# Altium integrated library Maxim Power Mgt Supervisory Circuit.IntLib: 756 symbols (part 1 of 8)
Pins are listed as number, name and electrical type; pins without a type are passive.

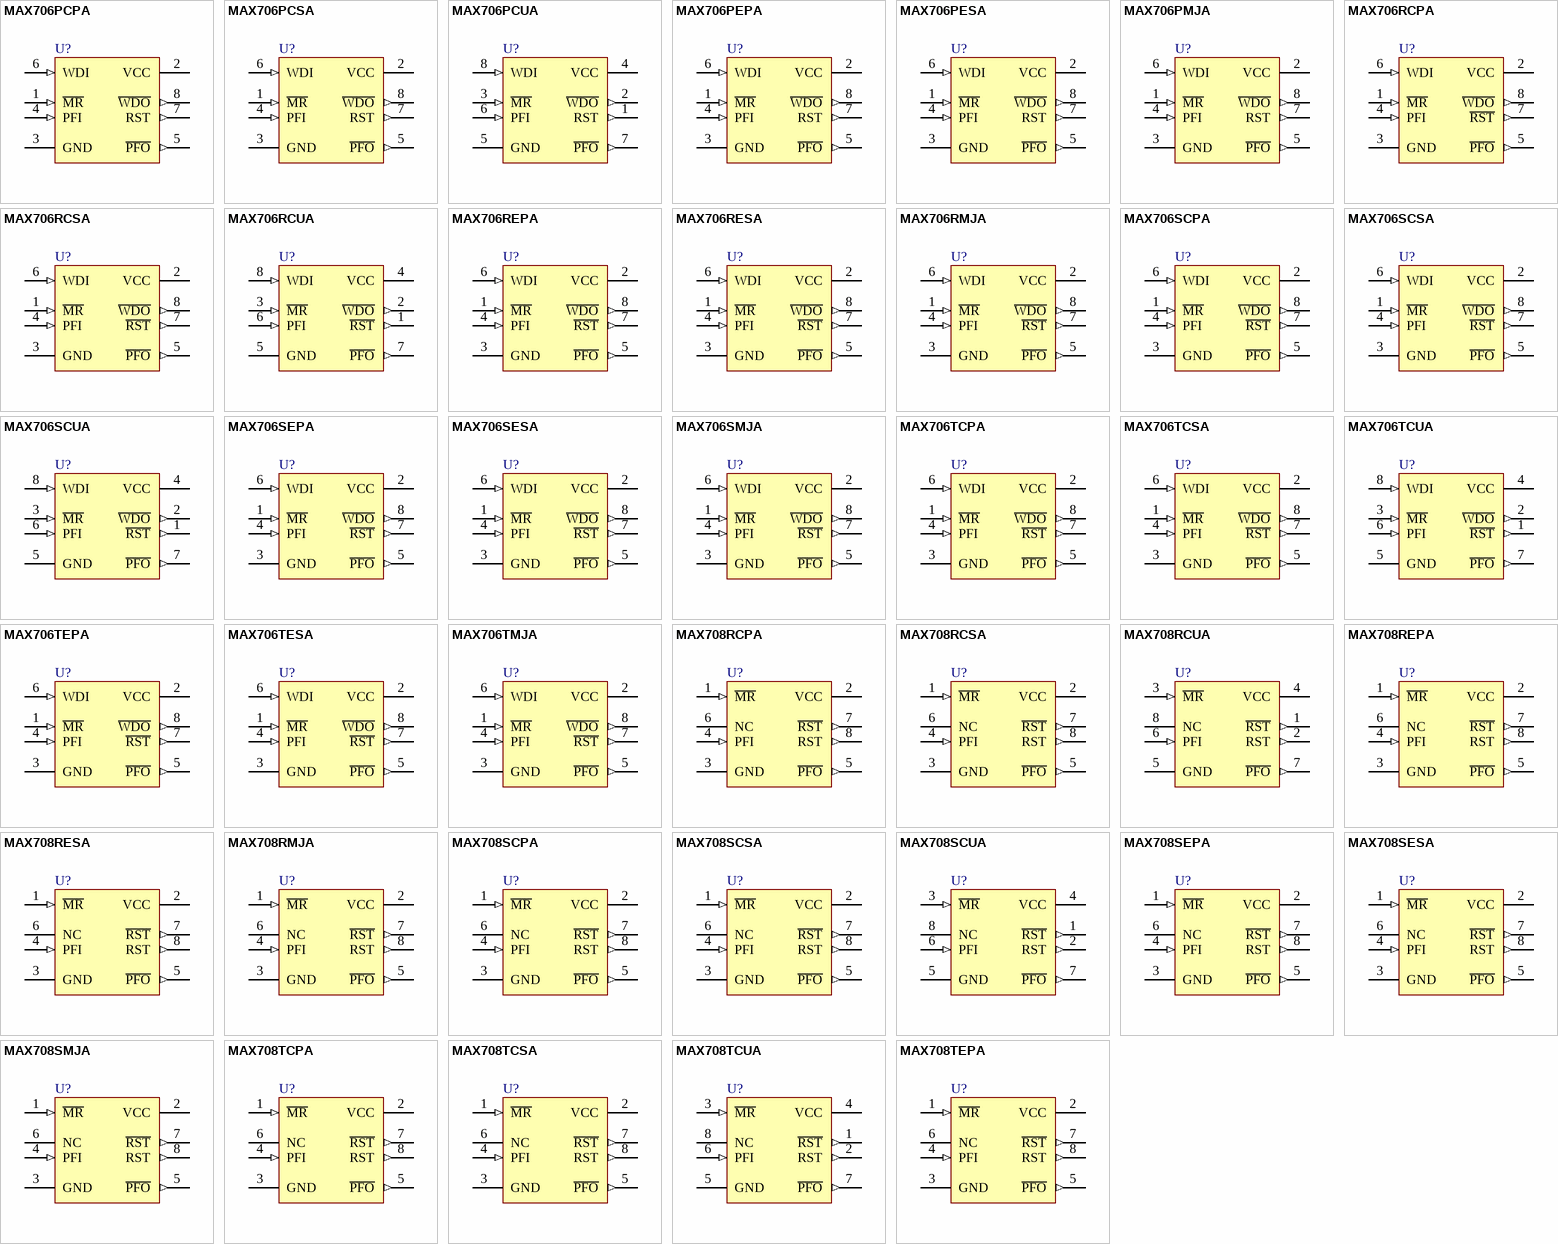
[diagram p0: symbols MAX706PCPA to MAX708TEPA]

## MAX706PCPA
designator U?
+3V Voltage Monitoring, Low-Cost, µP Supervisory Circuit
footprint PA8 (DIP, 8-Leads, Row Spacing 7.62mm, Pitch 2.54mm, Body 9.38x7.24mm)
3D model PA8 (DIP, 8-Pin, Row Spacing 7.62 mm, Pitch 2.54 mm)
pins: 1 ~{MR} (in), 2 VCC (power), 3 GND (power), 4 PFI (in), 5 ~{PFO} (out), 6 WDI (in), 7 RST (out), 8 ~{WDO} (out)

## MAX706PCSA
designator U?
+3V Voltage Monitoring, Low-Cost, µP Supervisory Circuit
footprint NSO8_N (SOIC, 8-Leads, Body 4.9x3.9mm, Pitch 1.27mm, IPC Medium Density)
footprint NSO8_L (SOIC, 8-Leads, Body 4.9x3.9mm, Pitch 1.27mm, IPC High Density)
footprint NSO8_M (SOIC, 8-Leads, Body 4.9x3.9mm, Pitch 1.27mm, IPC Low Density)
3D model NSO8 (8-Pin Small Outline Integrated Circuit 1.27 mm Pitch)
pins: 1 ~{MR} (in), 2 VCC (power), 3 GND (power), 4 PFI (in), 5 ~{PFO} (out), 6 WDI (in), 7 RST (out), 8 ~{WDO} (out)

## MAX706PCUA
designator U?
+3V Voltage Monitoring, Low-Cost, µP Supervisory Circuit
footprint UMAX8_N (TSOP, 8-Leads, Body 3x3mm, Pitch 0.65mm, IPC Medium Density)
footprint UMAX8_L (TSOP, 8-Leads, Body 3x3mm, Pitch 0.65mm, IPC High Density)
footprint UMAX8_M (TSOP, 8-Leads, Body 3x3mm, Pitch 0.65mm, IPC Low Density)
3D model UMAX8 (8-Pin Thin Small Outline Package 0.65 mm Pitch)
pins: 1 RST (out), 2 ~{WDO} (out), 3 ~{MR} (in), 4 VCC (power), 5 GND (power), 6 PFI (in), 7 ~{PFO} (out), 8 WDI (in)

## MAX706PEPA
designator U?
+3V Voltage Monitoring, Low-Cost, µP Supervisory Circuit
footprint PA8 (DIP, 8-Leads, Row Spacing 7.62mm, Pitch 2.54mm, Body 9.38x7.24mm)
3D model PA8 (DIP, 8-Pin, Row Spacing 7.62 mm, Pitch 2.54 mm)
pins: 1 ~{MR} (in), 2 VCC (power), 3 GND (power), 4 PFI (in), 5 ~{PFO} (out), 6 WDI (in), 7 RST (out), 8 ~{WDO} (out)

## MAX706PESA
designator U?
+3V Voltage Monitoring, Low-Cost, µP Supervisory Circuit
footprint NSO8_N (SOIC, 8-Leads, Body 4.9x3.9mm, Pitch 1.27mm, IPC Medium Density)
footprint NSO8_L (SOIC, 8-Leads, Body 4.9x3.9mm, Pitch 1.27mm, IPC High Density)
footprint NSO8_M (SOIC, 8-Leads, Body 4.9x3.9mm, Pitch 1.27mm, IPC Low Density)
3D model NSO8 (8-Pin Small Outline Integrated Circuit 1.27 mm Pitch)
pins: 1 ~{MR} (in), 2 VCC (power), 3 GND (power), 4 PFI (in), 5 ~{PFO} (out), 6 WDI (in), 7 RST (out), 8 ~{WDO} (out)

## MAX706PMJA
designator U?
+3V Voltage Monitoring, Low-Cost, µP Supervisory Circuit
footprint JA8 (DIP, 8-Leads, Row Spacing 7.62mm, Pitch 2.54mm, Body 9.91x6.73mm)
3D model PA8 (DIP, 8-Pin, Row Spacing 7.62 mm, Pitch 2.54 mm)
pins: 1 ~{MR} (in), 2 VCC (power), 3 GND (power), 4 PFI (in), 5 ~{PFO} (out), 6 WDI (in), 7 RST (out), 8 ~{WDO} (out)

## MAX706RCPA
designator U?
+3V Voltage Monitoring, Low-Cost, µP Supervisory Circuit
footprint PA8 (DIP, 8-Leads, Row Spacing 7.62mm, Pitch 2.54mm, Body 9.38x7.24mm)
3D model PA8 (DIP, 8-Pin, Row Spacing 7.62 mm, Pitch 2.54 mm)
pins: 1 ~{MR} (in), 2 VCC (power), 3 GND (power), 4 PFI (in), 5 ~{PFO} (out), 6 WDI (in), 7 ~{RST} (out), 8 ~{WDO} (out)

## MAX706RCSA
designator U?
+3V Voltage Monitoring, Low-Cost, µP Supervisory Circuit
footprint NSO8_N (SOIC, 8-Leads, Body 4.9x3.9mm, Pitch 1.27mm, IPC Medium Density)
footprint NSO8_L (SOIC, 8-Leads, Body 4.9x3.9mm, Pitch 1.27mm, IPC High Density)
footprint NSO8_M (SOIC, 8-Leads, Body 4.9x3.9mm, Pitch 1.27mm, IPC Low Density)
3D model NSO8 (8-Pin Small Outline Integrated Circuit 1.27 mm Pitch)
pins: 1 ~{MR} (in), 2 VCC (power), 3 GND (power), 4 PFI (in), 5 ~{PFO} (out), 6 WDI (in), 7 ~{RST} (out), 8 ~{WDO} (out)

## MAX706RCUA
designator U?
+3V Voltage Monitoring, Low-Cost, µP Supervisory Circuit
footprint UMAX8_N (TSOP, 8-Leads, Body 3x3mm, Pitch 0.65mm, IPC Medium Density)
footprint UMAX8_L (TSOP, 8-Leads, Body 3x3mm, Pitch 0.65mm, IPC High Density)
footprint UMAX8_M (TSOP, 8-Leads, Body 3x3mm, Pitch 0.65mm, IPC Low Density)
3D model UMAX8 (8-Pin Thin Small Outline Package 0.65 mm Pitch)
pins: 1 ~{RST} (out), 2 ~{WDO} (out), 3 ~{MR} (in), 4 VCC (power), 5 GND (power), 6 PFI (in), 7 ~{PFO} (out), 8 WDI (in)

## MAX706REPA
designator U?
+3V Voltage Monitoring, Low-Cost, µP Supervisory Circuit
footprint PA8 (DIP, 8-Leads, Row Spacing 7.62mm, Pitch 2.54mm, Body 9.38x7.24mm)
3D model PA8 (DIP, 8-Pin, Row Spacing 7.62 mm, Pitch 2.54 mm)
pins: 1 ~{MR} (in), 2 VCC (power), 3 GND (power), 4 PFI (in), 5 ~{PFO} (out), 6 WDI (in), 7 ~{RST} (out), 8 ~{WDO} (out)

## MAX706RESA
designator U?
+3V Voltage Monitoring, Low-Cost, µP Supervisory Circuit
footprint NSO8_N (SOIC, 8-Leads, Body 4.9x3.9mm, Pitch 1.27mm, IPC Medium Density)
footprint NSO8_L (SOIC, 8-Leads, Body 4.9x3.9mm, Pitch 1.27mm, IPC High Density)
footprint NSO8_M (SOIC, 8-Leads, Body 4.9x3.9mm, Pitch 1.27mm, IPC Low Density)
3D model NSO8 (8-Pin Small Outline Integrated Circuit 1.27 mm Pitch)
pins: 1 ~{MR} (in), 2 VCC (power), 3 GND (power), 4 PFI (in), 5 ~{PFO} (out), 6 WDI (in), 7 ~{RST} (out), 8 ~{WDO} (out)

## MAX706RMJA
designator U?
+3V Voltage Monitoring, Low-Cost, µP Supervisory Circuit
footprint JA8 (DIP, 8-Leads, Row Spacing 7.62mm, Pitch 2.54mm, Body 9.91x6.73mm)
3D model PA8 (DIP, 8-Pin, Row Spacing 7.62 mm, Pitch 2.54 mm)
pins: 1 ~{MR} (in), 2 VCC (power), 3 GND (power), 4 PFI (in), 5 ~{PFO} (out), 6 WDI (in), 7 ~{RST} (out), 8 ~{WDO} (out)

## MAX706SCPA
designator U?
+3V Voltage Monitoring, Low-Cost, µP Supervisory Circuit
footprint PA8 (DIP, 8-Leads, Row Spacing 7.62mm, Pitch 2.54mm, Body 9.38x7.24mm)
3D model PA8 (DIP, 8-Pin, Row Spacing 7.62 mm, Pitch 2.54 mm)
pins: 1 ~{MR} (in), 2 VCC (power), 3 GND (power), 4 PFI (in), 5 ~{PFO} (out), 6 WDI (in), 7 ~{RST} (out), 8 ~{WDO} (out)

## MAX706SCSA
designator U?
+3V Voltage Monitoring, Low-Cost, µP Supervisory Circuit
footprint NSO8_N (SOIC, 8-Leads, Body 4.9x3.9mm, Pitch 1.27mm, IPC Medium Density)
footprint NSO8_L (SOIC, 8-Leads, Body 4.9x3.9mm, Pitch 1.27mm, IPC High Density)
footprint NSO8_M (SOIC, 8-Leads, Body 4.9x3.9mm, Pitch 1.27mm, IPC Low Density)
3D model NSO8 (8-Pin Small Outline Integrated Circuit 1.27 mm Pitch)
pins: 1 ~{MR} (in), 2 VCC (power), 3 GND (power), 4 PFI (in), 5 ~{PFO} (out), 6 WDI (in), 7 ~{RST} (out), 8 ~{WDO} (out)

## MAX706SCUA
designator U?
+3V Voltage Monitoring, Low-Cost, µP Supervisory Circuit
footprint UMAX8_N (TSOP, 8-Leads, Body 3x3mm, Pitch 0.65mm, IPC Medium Density)
footprint UMAX8_L (TSOP, 8-Leads, Body 3x3mm, Pitch 0.65mm, IPC High Density)
footprint UMAX8_M (TSOP, 8-Leads, Body 3x3mm, Pitch 0.65mm, IPC Low Density)
3D model UMAX8 (8-Pin Thin Small Outline Package 0.65 mm Pitch)
pins: 1 ~{RST} (out), 2 ~{WDO} (out), 3 ~{MR} (in), 4 VCC (power), 5 GND (power), 6 PFI (in), 7 ~{PFO} (out), 8 WDI (in)

## MAX706SEPA
designator U?
+3V Voltage Monitoring, Low-Cost, µP Supervisory Circuit
footprint PA8 (DIP, 8-Leads, Row Spacing 7.62mm, Pitch 2.54mm, Body 9.38x7.24mm)
3D model PA8 (DIP, 8-Pin, Row Spacing 7.62 mm, Pitch 2.54 mm)
pins: 1 ~{MR} (in), 2 VCC (power), 3 GND (power), 4 PFI (in), 5 ~{PFO} (out), 6 WDI (in), 7 ~{RST} (out), 8 ~{WDO} (out)

## MAX706SESA
designator U?
+3V Voltage Monitoring, Low-Cost, µP Supervisory Circuit
footprint NSO8_N (SOIC, 8-Leads, Body 4.9x3.9mm, Pitch 1.27mm, IPC Medium Density)
footprint NSO8_L (SOIC, 8-Leads, Body 4.9x3.9mm, Pitch 1.27mm, IPC High Density)
footprint NSO8_M (SOIC, 8-Leads, Body 4.9x3.9mm, Pitch 1.27mm, IPC Low Density)
3D model NSO8 (8-Pin Small Outline Integrated Circuit 1.27 mm Pitch)
pins: 1 ~{MR} (in), 2 VCC (power), 3 GND (power), 4 PFI (in), 5 ~{PFO} (out), 6 WDI (in), 7 ~{RST} (out), 8 ~{WDO} (out)

## MAX706SMJA
designator U?
+3V Voltage Monitoring, Low-Cost, µP Supervisory Circuit
footprint JA8 (DIP, 8-Leads, Row Spacing 7.62mm, Pitch 2.54mm, Body 9.91x6.73mm)
3D model PA8 (DIP, 8-Pin, Row Spacing 7.62 mm, Pitch 2.54 mm)
pins: 1 ~{MR} (in), 2 VCC (power), 3 GND (power), 4 PFI (in), 5 ~{PFO} (out), 6 WDI (in), 7 ~{RST} (out), 8 ~{WDO} (out)

## MAX706TCPA
designator U?
+3V Voltage Monitoring, Low-Cost, µP Supervisory Circuit
footprint PA8 (DIP, 8-Leads, Row Spacing 7.62mm, Pitch 2.54mm, Body 9.38x7.24mm)
3D model PA8 (DIP, 8-Pin, Row Spacing 7.62 mm, Pitch 2.54 mm)
pins: 1 ~{MR} (in), 2 VCC (power), 3 GND (power), 4 PFI (in), 5 ~{PFO} (out), 6 WDI (in), 7 ~{RST} (out), 8 ~{WDO} (out)

## MAX706TCSA
designator U?
+3V Voltage Monitoring, Low-Cost, µP Supervisory Circuit
footprint NSO8_N (SOIC, 8-Leads, Body 4.9x3.9mm, Pitch 1.27mm, IPC Medium Density)
footprint NSO8_L (SOIC, 8-Leads, Body 4.9x3.9mm, Pitch 1.27mm, IPC High Density)
footprint NSO8_M (SOIC, 8-Leads, Body 4.9x3.9mm, Pitch 1.27mm, IPC Low Density)
3D model NSO8 (8-Pin Small Outline Integrated Circuit 1.27 mm Pitch)
pins: 1 ~{MR} (in), 2 VCC (power), 3 GND (power), 4 PFI (in), 5 ~{PFO} (out), 6 WDI (in), 7 ~{RST} (out), 8 ~{WDO} (out)

## MAX706TCUA
designator U?
+3V Voltage Monitoring, Low-Cost, µP Supervisory Circuit
footprint UMAX8_N (TSOP, 8-Leads, Body 3x3mm, Pitch 0.65mm, IPC Medium Density)
footprint UMAX8_L (TSOP, 8-Leads, Body 3x3mm, Pitch 0.65mm, IPC High Density)
footprint UMAX8_M (TSOP, 8-Leads, Body 3x3mm, Pitch 0.65mm, IPC Low Density)
3D model UMAX8 (8-Pin Thin Small Outline Package 0.65 mm Pitch)
pins: 1 ~{RST} (out), 2 ~{WDO} (out), 3 ~{MR} (in), 4 VCC (power), 5 GND (power), 6 PFI (in), 7 ~{PFO} (out), 8 WDI (in)

## MAX706TEPA
designator U?
+3V Voltage Monitoring, Low-Cost, µP Supervisory Circuit
footprint PA8 (DIP, 8-Leads, Row Spacing 7.62mm, Pitch 2.54mm, Body 9.38x7.24mm)
3D model PA8 (DIP, 8-Pin, Row Spacing 7.62 mm, Pitch 2.54 mm)
pins: 1 ~{MR} (in), 2 VCC (power), 3 GND (power), 4 PFI (in), 5 ~{PFO} (out), 6 WDI (in), 7 ~{RST} (out), 8 ~{WDO} (out)

## MAX706TESA
designator U?
+3V Voltage Monitoring, Low-Cost, µP Supervisory Circuit
footprint NSO8_N (SOIC, 8-Leads, Body 4.9x3.9mm, Pitch 1.27mm, IPC Medium Density)
footprint NSO8_L (SOIC, 8-Leads, Body 4.9x3.9mm, Pitch 1.27mm, IPC High Density)
footprint NSO8_M (SOIC, 8-Leads, Body 4.9x3.9mm, Pitch 1.27mm, IPC Low Density)
3D model NSO8 (8-Pin Small Outline Integrated Circuit 1.27 mm Pitch)
pins: 1 ~{MR} (in), 2 VCC (power), 3 GND (power), 4 PFI (in), 5 ~{PFO} (out), 6 WDI (in), 7 ~{RST} (out), 8 ~{WDO} (out)

## MAX706TMJA
designator U?
+3V Voltage Monitoring, Low-Cost, µP Supervisory Circuit
footprint JA8 (DIP, 8-Leads, Row Spacing 7.62mm, Pitch 2.54mm, Body 9.91x6.73mm)
3D model PA8 (DIP, 8-Pin, Row Spacing 7.62 mm, Pitch 2.54 mm)
pins: 1 ~{MR} (in), 2 VCC (power), 3 GND (power), 4 PFI (in), 5 ~{PFO} (out), 6 WDI (in), 7 ~{RST} (out), 8 ~{WDO} (out)

## MAX708RCPA
designator U?
+3V Voltage Monitoring, Low-Cost, µP Supervisory Circuit
footprint PA8 (DIP, 8-Leads, Row Spacing 7.62mm, Pitch 2.54mm, Body 9.38x7.24mm)
3D model PA8 (DIP, 8-Pin, Row Spacing 7.62 mm, Pitch 2.54 mm)
pins: 1 ~{MR} (in), 2 VCC (power), 3 GND (power), 4 PFI (in), 5 ~{PFO} (out), 6 NC, 7 ~{RST} (out), 8 RST (out)

## MAX708RCSA
designator U?
+3V Voltage Monitoring, Low-Cost, µP Supervisory Circuit
footprint NSO8_N (SOIC, 8-Leads, Body 4.9x3.9mm, Pitch 1.27mm, IPC Medium Density)
footprint NSO8_L (SOIC, 8-Leads, Body 4.9x3.9mm, Pitch 1.27mm, IPC High Density)
footprint NSO8_M (SOIC, 8-Leads, Body 4.9x3.9mm, Pitch 1.27mm, IPC Low Density)
3D model NSO8 (8-Pin Small Outline Integrated Circuit 1.27 mm Pitch)
pins: 1 ~{MR} (in), 2 VCC (power), 3 GND (power), 4 PFI (in), 5 ~{PFO} (out), 6 NC, 7 ~{RST} (out), 8 RST (out)

## MAX708RCUA
designator U?
+3V Voltage Monitoring, Low-Cost, µP Supervisory Circuit
footprint UMAX8_N (TSOP, 8-Leads, Body 3x3mm, Pitch 0.65mm, IPC Medium Density)
footprint UMAX8_L (TSOP, 8-Leads, Body 3x3mm, Pitch 0.65mm, IPC High Density)
footprint UMAX8_M (TSOP, 8-Leads, Body 3x3mm, Pitch 0.65mm, IPC Low Density)
3D model UMAX8 (8-Pin Thin Small Outline Package 0.65 mm Pitch)
pins: 1 ~{RST} (out), 2 RST (out), 3 ~{MR} (in), 4 VCC (power), 5 GND (power), 6 PFI (in), 7 ~{PFO} (out), 8 NC

## MAX708REPA
designator U?
+3V Voltage Monitoring, Low-Cost, µP Supervisory Circuit
footprint PA8 (DIP, 8-Leads, Row Spacing 7.62mm, Pitch 2.54mm, Body 9.38x7.24mm)
3D model PA8 (DIP, 8-Pin, Row Spacing 7.62 mm, Pitch 2.54 mm)
pins: 1 ~{MR} (in), 2 VCC (power), 3 GND (power), 4 PFI (in), 5 ~{PFO} (out), 6 NC, 7 ~{RST} (out), 8 RST (out)

## MAX708RESA
designator U?
+3V Voltage Monitoring, Low-Cost, µP Supervisory Circuit
footprint NSO8_N (SOIC, 8-Leads, Body 4.9x3.9mm, Pitch 1.27mm, IPC Medium Density)
footprint NSO8_L (SOIC, 8-Leads, Body 4.9x3.9mm, Pitch 1.27mm, IPC High Density)
footprint NSO8_M (SOIC, 8-Leads, Body 4.9x3.9mm, Pitch 1.27mm, IPC Low Density)
3D model NSO8 (8-Pin Small Outline Integrated Circuit 1.27 mm Pitch)
pins: 1 ~{MR} (in), 2 VCC (power), 3 GND (power), 4 PFI (in), 5 ~{PFO} (out), 6 NC, 7 ~{RST} (out), 8 RST (out)

## MAX708RMJA
designator U?
+3V Voltage Monitoring, Low-Cost, µP Supervisory Circuit
footprint JA8 (DIP, 8-Leads, Row Spacing 7.62mm, Pitch 2.54mm, Body 9.91x6.73mm)
3D model PA8 (DIP, 8-Pin, Row Spacing 7.62 mm, Pitch 2.54 mm)
pins: 1 ~{MR} (in), 2 VCC (power), 3 GND (power), 4 PFI (in), 5 ~{PFO} (out), 6 NC, 7 ~{RST} (out), 8 RST (out)

## MAX708SCPA
designator U?
+3V Voltage Monitoring, Low-Cost, µP Supervisory Circuit
footprint PA8 (DIP, 8-Leads, Row Spacing 7.62mm, Pitch 2.54mm, Body 9.38x7.24mm)
3D model PA8 (DIP, 8-Pin, Row Spacing 7.62 mm, Pitch 2.54 mm)
pins: 1 ~{MR} (in), 2 VCC (power), 3 GND (power), 4 PFI (in), 5 ~{PFO} (out), 6 NC, 7 ~{RST} (out), 8 RST (out)

## MAX708SCSA
designator U?
+3V Voltage Monitoring, Low-Cost, µP Supervisory Circuit
footprint NSO8_N (SOIC, 8-Leads, Body 4.9x3.9mm, Pitch 1.27mm, IPC Medium Density)
footprint NSO8_L (SOIC, 8-Leads, Body 4.9x3.9mm, Pitch 1.27mm, IPC High Density)
footprint NSO8_M (SOIC, 8-Leads, Body 4.9x3.9mm, Pitch 1.27mm, IPC Low Density)
3D model NSO8 (8-Pin Small Outline Integrated Circuit 1.27 mm Pitch)
pins: 1 ~{MR} (in), 2 VCC (power), 3 GND (power), 4 PFI (in), 5 ~{PFO} (out), 6 NC, 7 ~{RST} (out), 8 RST (out)

## MAX708SCUA
designator U?
+3V Voltage Monitoring, Low-Cost, µP Supervisory Circuit
footprint UMAX8_N (TSOP, 8-Leads, Body 3x3mm, Pitch 0.65mm, IPC Medium Density)
footprint UMAX8_L (TSOP, 8-Leads, Body 3x3mm, Pitch 0.65mm, IPC High Density)
footprint UMAX8_M (TSOP, 8-Leads, Body 3x3mm, Pitch 0.65mm, IPC Low Density)
3D model UMAX8 (8-Pin Thin Small Outline Package 0.65 mm Pitch)
pins: 1 ~{RST} (out), 2 RST (out), 3 ~{MR} (in), 4 VCC (power), 5 GND (power), 6 PFI (in), 7 ~{PFO} (out), 8 NC

## MAX708SEPA
designator U?
+3V Voltage Monitoring, Low-Cost, µP Supervisory Circuit
footprint PA8 (DIP, 8-Leads, Row Spacing 7.62mm, Pitch 2.54mm, Body 9.38x7.24mm)
3D model PA8 (DIP, 8-Pin, Row Spacing 7.62 mm, Pitch 2.54 mm)
pins: 1 ~{MR} (in), 2 VCC (power), 3 GND (power), 4 PFI (in), 5 ~{PFO} (out), 6 NC, 7 ~{RST} (out), 8 RST (out)

## MAX708SESA
designator U?
+3V Voltage Monitoring, Low-Cost, µP Supervisory Circuit
footprint NSO8_N (SOIC, 8-Leads, Body 4.9x3.9mm, Pitch 1.27mm, IPC Medium Density)
footprint NSO8_L (SOIC, 8-Leads, Body 4.9x3.9mm, Pitch 1.27mm, IPC High Density)
footprint NSO8_M (SOIC, 8-Leads, Body 4.9x3.9mm, Pitch 1.27mm, IPC Low Density)
3D model NSO8 (8-Pin Small Outline Integrated Circuit 1.27 mm Pitch)
pins: 1 ~{MR} (in), 2 VCC (power), 3 GND (power), 4 PFI (in), 5 ~{PFO} (out), 6 NC, 7 ~{RST} (out), 8 RST (out)

## MAX708SMJA
designator U?
+3V Voltage Monitoring, Low-Cost, µP Supervisory Circuit
footprint JA8 (DIP, 8-Leads, Row Spacing 7.62mm, Pitch 2.54mm, Body 9.91x6.73mm)
3D model PA8 (DIP, 8-Pin, Row Spacing 7.62 mm, Pitch 2.54 mm)
pins: 1 ~{MR} (in), 2 VCC (power), 3 GND (power), 4 PFI (in), 5 ~{PFO} (out), 6 NC, 7 ~{RST} (out), 8 RST (out)

## MAX708TCPA
designator U?
+3V Voltage Monitoring, Low-Cost, µP Supervisory Circuit
footprint PA8 (DIP, 8-Leads, Row Spacing 7.62mm, Pitch 2.54mm, Body 9.38x7.24mm)
3D model PA8 (DIP, 8-Pin, Row Spacing 7.62 mm, Pitch 2.54 mm)
pins: 1 ~{MR} (in), 2 VCC (power), 3 GND (power), 4 PFI (in), 5 ~{PFO} (out), 6 NC, 7 ~{RST} (out), 8 RST (out)

## MAX708TCSA
designator U?
+3V Voltage Monitoring, Low-Cost, µP Supervisory Circuit
footprint NSO8_N (SOIC, 8-Leads, Body 4.9x3.9mm, Pitch 1.27mm, IPC Medium Density)
footprint NSO8_L (SOIC, 8-Leads, Body 4.9x3.9mm, Pitch 1.27mm, IPC High Density)
footprint NSO8_M (SOIC, 8-Leads, Body 4.9x3.9mm, Pitch 1.27mm, IPC Low Density)
3D model NSO8 (8-Pin Small Outline Integrated Circuit 1.27 mm Pitch)
pins: 1 ~{MR} (in), 2 VCC (power), 3 GND (power), 4 PFI (in), 5 ~{PFO} (out), 6 NC, 7 ~{RST} (out), 8 RST (out)

## MAX708TCUA
designator U?
+3V Voltage Monitoring, Low-Cost, µP Supervisory Circuit
footprint UMAX8_N (TSOP, 8-Leads, Body 3x3mm, Pitch 0.65mm, IPC Medium Density)
footprint UMAX8_L (TSOP, 8-Leads, Body 3x3mm, Pitch 0.65mm, IPC High Density)
footprint UMAX8_M (TSOP, 8-Leads, Body 3x3mm, Pitch 0.65mm, IPC Low Density)
3D model UMAX8 (8-Pin Thin Small Outline Package 0.65 mm Pitch)
pins: 1 ~{RST} (out), 2 RST (out), 3 ~{MR} (in), 4 VCC (power), 5 GND (power), 6 PFI (in), 7 ~{PFO} (out), 8 NC

## MAX708TEPA
designator U?
+3V Voltage Monitoring, Low-Cost, µP Supervisory Circuit
footprint PA8 (DIP, 8-Leads, Row Spacing 7.62mm, Pitch 2.54mm, Body 9.38x7.24mm)
3D model PA8 (DIP, 8-Pin, Row Spacing 7.62 mm, Pitch 2.54 mm)
pins: 1 ~{MR} (in), 2 VCC (power), 3 GND (power), 4 PFI (in), 5 ~{PFO} (out), 6 NC, 7 ~{RST} (out), 8 RST (out)

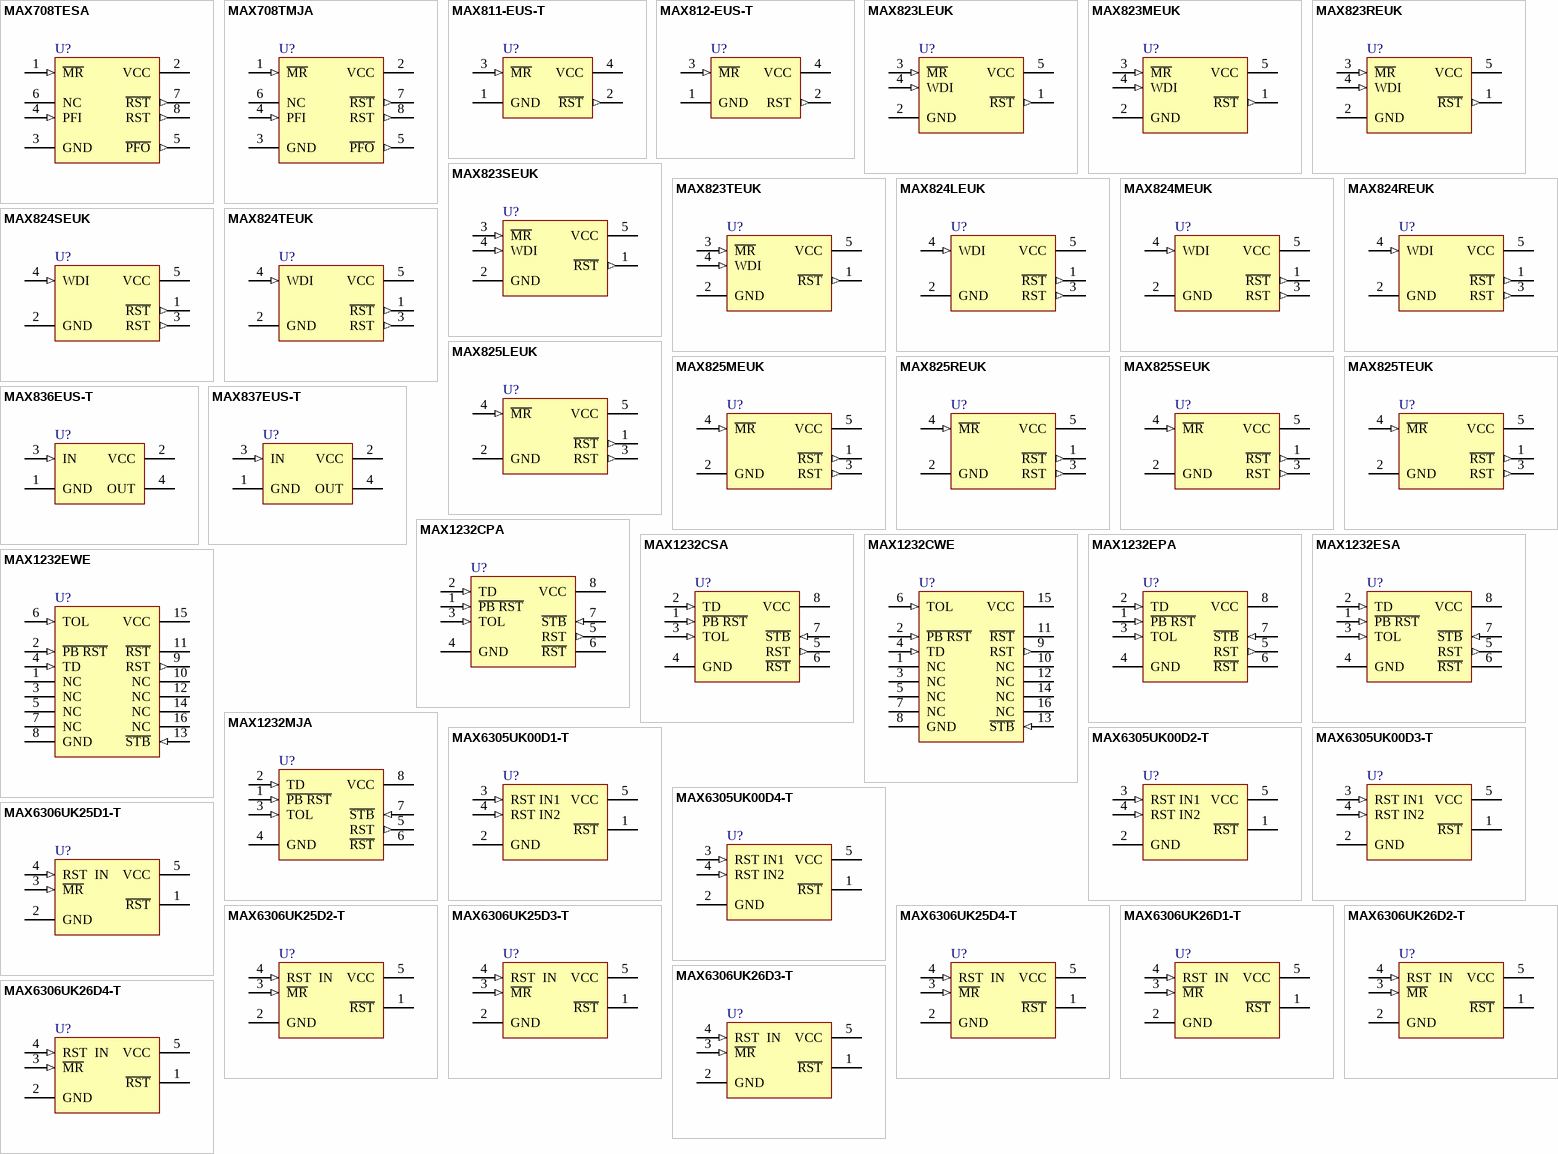
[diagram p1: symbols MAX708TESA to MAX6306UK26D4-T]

## MAX708TESA
designator U?
+3V Voltage Monitoring, Low-Cost, µP Supervisory Circuit
footprint NSO8_N (SOIC, 8-Leads, Body 4.9x3.9mm, Pitch 1.27mm, IPC Medium Density)
footprint NSO8_L (SOIC, 8-Leads, Body 4.9x3.9mm, Pitch 1.27mm, IPC High Density)
footprint NSO8_M (SOIC, 8-Leads, Body 4.9x3.9mm, Pitch 1.27mm, IPC Low Density)
3D model NSO8 (8-Pin Small Outline Integrated Circuit 1.27 mm Pitch)
pins: 1 ~{MR} (in), 2 VCC (power), 3 GND (power), 4 PFI (in), 5 ~{PFO} (out), 6 NC, 7 ~{RST} (out), 8 RST (out)

## MAX708TMJA
designator U?
+3V Voltage Monitoring, Low-Cost, µP Supervisory Circuit
footprint JA8 (DIP, 8-Leads, Row Spacing 7.62mm, Pitch 2.54mm, Body 9.91x6.73mm)
3D model PA8 (DIP, 8-Pin, Row Spacing 7.62 mm, Pitch 2.54 mm)
pins: 1 ~{MR} (in), 2 VCC (power), 3 GND (power), 4 PFI (in), 5 ~{PFO} (out), 6 NC, 7 ~{RST} (out), 8 RST (out)

## MAX811-EUS-T
designator U?
4-Pin µP Voltage Monitors with Manual Reset Input
footprint SOT143_N (SOT143, 4-Leads, Body 2.9x1.3mm, Pitch 1.9mm, Lead Span 2.3mm, IPC Medium Density)
footprint SOT143_L (SOT143, 4-Leads, Body 2.9x1.3mm, Pitch 1.9mm, Lead Span 2.3mm, IPC High Density)
footprint SOT143_M (SOT143, 4-Leads, Body 2.9x1.3mm, Pitch 1.9mm, Lead Span 2.3mm, IPC Low Density)
pins: 1 GND (power), 2 ~{RST} (out), 3 ~{MR} (in), 4 VCC (power)

## MAX812-EUS-T
designator U?
4-Pin µP Voltage Monitors with Manual Reset Input
footprint SOT143_N (SOT143, 4-Leads, Body 2.9x1.3mm, Pitch 1.9mm, Lead Span 2.3mm, IPC Medium Density)
footprint SOT143_L (SOT143, 4-Leads, Body 2.9x1.3mm, Pitch 1.9mm, Lead Span 2.3mm, IPC High Density)
footprint SOT143_M (SOT143, 4-Leads, Body 2.9x1.3mm, Pitch 1.9mm, Lead Span 2.3mm, IPC Low Density)
pins: 1 GND (power), 2 RST (out), 3 ~{MR} (in), 4 VCC (power)

## MAX823LEUK
designator U?
5-Pin Microprocessor Supervisory Circuit
footprint SOT23-5_N (SOT23, 5-Leads, Body 2.9x1.6mm, Pitch 0.95mm, Lead Span 2.8mm, IPC Medium Density)
footprint SOT23-5_L (SOT23, 5-Leads, Body 2.9x1.6mm, Pitch 0.95mm, Lead Span 2.8mm, IPC High Density)
footprint SOT23-5_M (SOT23, 5-Leads, Body 2.9x1.6mm, Pitch 0.95mm, Lead Span 2.8mm, IPC Low Density)
pins: 1 ~{RST} (out), 2 GND (power), 3 ~{MR} (in), 4 WDI (in), 5 VCC (power)

## MAX823MEUK
designator U?
5-Pin Microprocessor Supervisory Circuit
footprint SOT23-5_N (SOT23, 5-Leads, Body 2.9x1.6mm, Pitch 0.95mm, Lead Span 2.8mm, IPC Medium Density)
footprint SOT23-5_L (SOT23, 5-Leads, Body 2.9x1.6mm, Pitch 0.95mm, Lead Span 2.8mm, IPC High Density)
footprint SOT23-5_M (SOT23, 5-Leads, Body 2.9x1.6mm, Pitch 0.95mm, Lead Span 2.8mm, IPC Low Density)
pins: 1 ~{RST} (out), 2 GND (power), 3 ~{MR} (in), 4 WDI (in), 5 VCC (power)

## MAX823REUK
designator U?
5-Pin Microprocessor Supervisory Circuit
footprint SOT23-5_N (SOT23, 5-Leads, Body 2.9x1.6mm, Pitch 0.95mm, Lead Span 2.8mm, IPC Medium Density)
footprint SOT23-5_L (SOT23, 5-Leads, Body 2.9x1.6mm, Pitch 0.95mm, Lead Span 2.8mm, IPC High Density)
footprint SOT23-5_M (SOT23, 5-Leads, Body 2.9x1.6mm, Pitch 0.95mm, Lead Span 2.8mm, IPC Low Density)
pins: 1 ~{RST} (out), 2 GND (power), 3 ~{MR} (in), 4 WDI (in), 5 VCC (power)

## MAX823SEUK
designator U?
5-Pin Microprocessor Supervisory Circuit
footprint SOT23-5_N (SOT23, 5-Leads, Body 2.9x1.6mm, Pitch 0.95mm, Lead Span 2.8mm, IPC Medium Density)
footprint SOT23-5_L (SOT23, 5-Leads, Body 2.9x1.6mm, Pitch 0.95mm, Lead Span 2.8mm, IPC High Density)
footprint SOT23-5_M (SOT23, 5-Leads, Body 2.9x1.6mm, Pitch 0.95mm, Lead Span 2.8mm, IPC Low Density)
pins: 1 ~{RST} (out), 2 GND (power), 3 ~{MR} (in), 4 WDI (in), 5 VCC (power)

## MAX823TEUK
designator U?
5-Pin Microprocessor Supervisory Circuit
footprint SOT23-5_N (SOT23, 5-Leads, Body 2.9x1.6mm, Pitch 0.95mm, Lead Span 2.8mm, IPC Medium Density)
footprint SOT23-5_L (SOT23, 5-Leads, Body 2.9x1.6mm, Pitch 0.95mm, Lead Span 2.8mm, IPC High Density)
footprint SOT23-5_M (SOT23, 5-Leads, Body 2.9x1.6mm, Pitch 0.95mm, Lead Span 2.8mm, IPC Low Density)
pins: 1 ~{RST} (out), 2 GND (power), 3 ~{MR} (in), 4 WDI (in), 5 VCC (power)

## MAX824LEUK
designator U?
5-Pin Microprocessor Supervisory Circuit
footprint SOT23-5_N (SOT23, 5-Leads, Body 2.9x1.6mm, Pitch 0.95mm, Lead Span 2.8mm, IPC Medium Density)
footprint SOT23-5_L (SOT23, 5-Leads, Body 2.9x1.6mm, Pitch 0.95mm, Lead Span 2.8mm, IPC High Density)
footprint SOT23-5_M (SOT23, 5-Leads, Body 2.9x1.6mm, Pitch 0.95mm, Lead Span 2.8mm, IPC Low Density)
pins: 1 ~{RST} (out), 2 GND (power), 3 RST (out), 4 WDI (in), 5 VCC (power)

## MAX824MEUK
designator U?
5-Pin Microprocessor Supervisory Circuit
footprint SOT23-5_N (SOT23, 5-Leads, Body 2.9x1.6mm, Pitch 0.95mm, Lead Span 2.8mm, IPC Medium Density)
footprint SOT23-5_L (SOT23, 5-Leads, Body 2.9x1.6mm, Pitch 0.95mm, Lead Span 2.8mm, IPC High Density)
footprint SOT23-5_M (SOT23, 5-Leads, Body 2.9x1.6mm, Pitch 0.95mm, Lead Span 2.8mm, IPC Low Density)
pins: 1 ~{RST} (out), 2 GND (power), 3 RST (out), 4 WDI (in), 5 VCC (power)

## MAX824REUK
designator U?
5-Pin Microprocessor Supervisory Circuit
footprint SOT23-5_N (SOT23, 5-Leads, Body 2.9x1.6mm, Pitch 0.95mm, Lead Span 2.8mm, IPC Medium Density)
footprint SOT23-5_L (SOT23, 5-Leads, Body 2.9x1.6mm, Pitch 0.95mm, Lead Span 2.8mm, IPC High Density)
footprint SOT23-5_M (SOT23, 5-Leads, Body 2.9x1.6mm, Pitch 0.95mm, Lead Span 2.8mm, IPC Low Density)
pins: 1 ~{RST} (out), 2 GND (power), 3 RST (out), 4 WDI (in), 5 VCC (power)

## MAX824SEUK
designator U?
5-Pin Microprocessor Supervisory Circuit
footprint SOT23-5_N (SOT23, 5-Leads, Body 2.9x1.6mm, Pitch 0.95mm, Lead Span 2.8mm, IPC Medium Density)
footprint SOT23-5_L (SOT23, 5-Leads, Body 2.9x1.6mm, Pitch 0.95mm, Lead Span 2.8mm, IPC High Density)
footprint SOT23-5_M (SOT23, 5-Leads, Body 2.9x1.6mm, Pitch 0.95mm, Lead Span 2.8mm, IPC Low Density)
pins: 1 ~{RST} (out), 2 GND (power), 3 RST (out), 4 WDI (in), 5 VCC (power)

## MAX824TEUK
designator U?
5-Pin Microprocessor Supervisory Circuit
footprint SOT23-5_N (SOT23, 5-Leads, Body 2.9x1.6mm, Pitch 0.95mm, Lead Span 2.8mm, IPC Medium Density)
footprint SOT23-5_L (SOT23, 5-Leads, Body 2.9x1.6mm, Pitch 0.95mm, Lead Span 2.8mm, IPC High Density)
footprint SOT23-5_M (SOT23, 5-Leads, Body 2.9x1.6mm, Pitch 0.95mm, Lead Span 2.8mm, IPC Low Density)
pins: 1 ~{RST} (out), 2 GND (power), 3 RST (out), 4 WDI (in), 5 VCC (power)

## MAX825LEUK
designator U?
5-Pin Microprocessor Supervisory Circuit
footprint SOT23-5_N (SOT23, 5-Leads, Body 2.9x1.6mm, Pitch 0.95mm, Lead Span 2.8mm, IPC Medium Density)
footprint SOT23-5_L (SOT23, 5-Leads, Body 2.9x1.6mm, Pitch 0.95mm, Lead Span 2.8mm, IPC High Density)
footprint SOT23-5_M (SOT23, 5-Leads, Body 2.9x1.6mm, Pitch 0.95mm, Lead Span 2.8mm, IPC Low Density)
pins: 1 ~{RST} (out), 2 GND (power), 3 RST (out), 4 ~{MR} (in), 5 VCC (power)

## MAX825MEUK
designator U?
5-Pin Microprocessor Supervisory Circuit
footprint SOT23-5_N (SOT23, 5-Leads, Body 2.9x1.6mm, Pitch 0.95mm, Lead Span 2.8mm, IPC Medium Density)
footprint SOT23-5_L (SOT23, 5-Leads, Body 2.9x1.6mm, Pitch 0.95mm, Lead Span 2.8mm, IPC High Density)
footprint SOT23-5_M (SOT23, 5-Leads, Body 2.9x1.6mm, Pitch 0.95mm, Lead Span 2.8mm, IPC Low Density)
pins: 1 ~{RST} (out), 2 GND (power), 3 RST (out), 4 ~{MR} (in), 5 VCC (power)

## MAX825REUK
designator U?
5-Pin Microprocessor Supervisory Circuit
footprint SOT23-5_N (SOT23, 5-Leads, Body 2.9x1.6mm, Pitch 0.95mm, Lead Span 2.8mm, IPC Medium Density)
footprint SOT23-5_L (SOT23, 5-Leads, Body 2.9x1.6mm, Pitch 0.95mm, Lead Span 2.8mm, IPC High Density)
footprint SOT23-5_M (SOT23, 5-Leads, Body 2.9x1.6mm, Pitch 0.95mm, Lead Span 2.8mm, IPC Low Density)
pins: 1 ~{RST} (out), 2 GND (power), 3 RST (out), 4 ~{MR} (in), 5 VCC (power)

## MAX825SEUK
designator U?
5-Pin Microprocessor Supervisory Circuit
footprint SOT23-5_N (SOT23, 5-Leads, Body 2.9x1.6mm, Pitch 0.95mm, Lead Span 2.8mm, IPC Medium Density)
footprint SOT23-5_L (SOT23, 5-Leads, Body 2.9x1.6mm, Pitch 0.95mm, Lead Span 2.8mm, IPC High Density)
footprint SOT23-5_M (SOT23, 5-Leads, Body 2.9x1.6mm, Pitch 0.95mm, Lead Span 2.8mm, IPC Low Density)
pins: 1 ~{RST} (out), 2 GND (power), 3 RST (out), 4 ~{MR} (in), 5 VCC (power)

## MAX825TEUK
designator U?
5-Pin Microprocessor Supervisory Circuit
footprint SOT23-5_N (SOT23, 5-Leads, Body 2.9x1.6mm, Pitch 0.95mm, Lead Span 2.8mm, IPC Medium Density)
footprint SOT23-5_L (SOT23, 5-Leads, Body 2.9x1.6mm, Pitch 0.95mm, Lead Span 2.8mm, IPC High Density)
footprint SOT23-5_M (SOT23, 5-Leads, Body 2.9x1.6mm, Pitch 0.95mm, Lead Span 2.8mm, IPC Low Density)
pins: 1 ~{RST} (out), 2 GND (power), 3 RST (out), 4 ~{MR} (in), 5 VCC (power)

## MAX836EUS-T
designator U?
4-Pin Micropower Voltage Monitor
footprint SOT143_N (SOT143, 4-Leads, Body 2.9x1.3mm, Pitch 1.9mm, Lead Span 2.3mm, IPC Medium Density)
footprint SOT143_L (SOT143, 4-Leads, Body 2.9x1.3mm, Pitch 1.9mm, Lead Span 2.3mm, IPC High Density)
footprint SOT143_M (SOT143, 4-Leads, Body 2.9x1.3mm, Pitch 1.9mm, Lead Span 2.3mm, IPC Low Density)
pins: 1 GND (power), 2 VCC (power), 3 IN (in), 4 OUT (oc)

## MAX837EUS-T
designator U?
4-Pin Micropower Voltage Monitor
footprint SOT143_N (SOT143, 4-Leads, Body 2.9x1.3mm, Pitch 1.9mm, Lead Span 2.3mm, IPC Medium Density)
footprint SOT143_L (SOT143, 4-Leads, Body 2.9x1.3mm, Pitch 1.9mm, Lead Span 2.3mm, IPC High Density)
footprint SOT143_M (SOT143, 4-Leads, Body 2.9x1.3mm, Pitch 1.9mm, Lead Span 2.3mm, IPC Low Density)
pins: 1 GND (power), 2 VCC (power), 3 IN (in), 4 OUT (oc)

## MAX1232CPA
designator U?
Microprocessor Monitor
footprint PA8 (DIP, 8-Leads, Row Spacing 7.62mm, Pitch 2.54mm, Body 9.38x7.24mm)
3D model PA8 (DIP, 8-Pin, Row Spacing 7.62 mm, Pitch 2.54 mm)
pins: 1 ~{PB RST} (in), 2 TD (in), 3 TOL (in), 4 GND (power), 5 RST (out), 6 ~{RST} (oc), 7 ~{STB} (in), 8 VCC (power)

## MAX1232CSA
designator U?
Microprocessor Monitor
footprint NSO8_N (SOIC, 8-Leads, Body 4.9x3.9mm, Pitch 1.27mm, IPC Medium Density)
footprint NSO8_L (SOIC, 8-Leads, Body 4.9x3.9mm, Pitch 1.27mm, IPC High Density)
footprint NSO8_M (SOIC, 8-Leads, Body 4.9x3.9mm, Pitch 1.27mm, IPC Low Density)
3D model NSO8 (8-Pin Small Outline Integrated Circuit 1.27 mm Pitch)
pins: 1 ~{PB RST} (in), 2 TD (in), 3 TOL (in), 4 GND (power), 5 RST (out), 6 ~{RST} (oc), 7 ~{STB} (in), 8 VCC (power)

## MAX1232CWE
designator U?
Microprocessor Monitor
footprint WSO16_N (SOIC, 16-Leads, Body 10.3x7.5mm, Pitch 1.27mm, IPC Medium Density)
footprint WSO16_L (SOIC, 16-Leads, Body 10.3x7.5mm, Pitch 1.27mm, IPC High Density)
footprint WSO16_M (SOIC, 16-Leads, Body 10.3x7.5mm, Pitch 1.27mm, IPC Low Density)
3D model WSO16 (16-Pin Small Outline Integrated Circuit 1.27 mm Pitch)
pins: 1 NC, 2 ~{PB RST} (in), 3 NC, 4 TD (in), 5 NC, 6 TOL (in), 7 NC, 8 GND (power), 9 RST (out), 10 NC, 11 ~{RST} (oc), 12 NC, 13 ~{STB} (in), 14 NC, 15 VCC (power), 16 NC

## MAX1232EPA
designator U?
Microprocessor Monitor
footprint PA8 (DIP, 8-Leads, Row Spacing 7.62mm, Pitch 2.54mm, Body 9.38x7.24mm)
3D model PA8 (DIP, 8-Pin, Row Spacing 7.62 mm, Pitch 2.54 mm)
pins: 1 ~{PB RST} (in), 2 TD (in), 3 TOL (in), 4 GND (power), 5 RST (out), 6 ~{RST} (oc), 7 ~{STB} (in), 8 VCC (power)

## MAX1232ESA
designator U?
Microprocessor Monitor
footprint NSO8_N (SOIC, 8-Leads, Body 4.9x3.9mm, Pitch 1.27mm, IPC Medium Density)
footprint NSO8_L (SOIC, 8-Leads, Body 4.9x3.9mm, Pitch 1.27mm, IPC High Density)
footprint NSO8_M (SOIC, 8-Leads, Body 4.9x3.9mm, Pitch 1.27mm, IPC Low Density)
3D model NSO8 (8-Pin Small Outline Integrated Circuit 1.27 mm Pitch)
pins: 1 ~{PB RST} (in), 2 TD (in), 3 TOL (in), 4 GND (power), 5 RST (out), 6 ~{RST} (oc), 7 ~{STB} (in), 8 VCC (power)

## MAX1232EWE
designator U?
Microprocessor Monitor
footprint WSO16_N (SOIC, 16-Leads, Body 10.3x7.5mm, Pitch 1.27mm, IPC Medium Density)
footprint WSO16_L (SOIC, 16-Leads, Body 10.3x7.5mm, Pitch 1.27mm, IPC High Density)
footprint WSO16_M (SOIC, 16-Leads, Body 10.3x7.5mm, Pitch 1.27mm, IPC Low Density)
3D model WSO16 (16-Pin Small Outline Integrated Circuit 1.27 mm Pitch)
pins: 1 NC, 2 ~{PB RST} (in), 3 NC, 4 TD (in), 5 NC, 6 TOL (in), 7 NC, 8 GND (power), 9 RST (out), 10 NC, 11 ~{RST} (oc), 12 NC, 13 ~{STB} (in), 14 NC, 15 VCC (power), 16 NC

## MAX1232MJA
designator U?
Microprocessor Monitor
footprint JA8 (DIP, 8-Leads, Row Spacing 7.62mm, Pitch 2.54mm, Body 9.91x6.73mm)
3D model PA8 (DIP, 8-Pin, Row Spacing 7.62 mm, Pitch 2.54 mm)
pins: 1 ~{PB RST} (in), 2 TD (in), 3 TOL (in), 4 GND (power), 5 RST (out), 6 ~{RST} (oc), 7 ~{STB} (in), 8 VCC (power)

## MAX6305UK00D1-T
designator U?
5-Pin, Multiple-Input, Programmable Reset IC
footprint SOT23-5_N (SOT23, 5-Leads, Body 2.9x1.6mm, Pitch 0.95mm, Lead Span 2.8mm, IPC Medium Density)
footprint SOT23-5_L (SOT23, 5-Leads, Body 2.9x1.6mm, Pitch 0.95mm, Lead Span 2.8mm, IPC High Density)
footprint SOT23-5_M (SOT23, 5-Leads, Body 2.9x1.6mm, Pitch 0.95mm, Lead Span 2.8mm, IPC Low Density)
pins: 1 ~{RST} (oc), 2 GND (power), 3 RST IN1 (in), 4 RST IN2 (in), 5 VCC (power)

## MAX6305UK00D2-T
designator U?
5-Pin, Multiple-Input, Programmable Reset IC
footprint SOT23-5_N (SOT23, 5-Leads, Body 2.9x1.6mm, Pitch 0.95mm, Lead Span 2.8mm, IPC Medium Density)
footprint SOT23-5_L (SOT23, 5-Leads, Body 2.9x1.6mm, Pitch 0.95mm, Lead Span 2.8mm, IPC High Density)
footprint SOT23-5_M (SOT23, 5-Leads, Body 2.9x1.6mm, Pitch 0.95mm, Lead Span 2.8mm, IPC Low Density)
pins: 1 ~{RST} (oc), 2 GND (power), 3 RST IN1 (in), 4 RST IN2 (in), 5 VCC (power)

## MAX6305UK00D3-T
designator U?
5-Pin, Multiple-Input, Programmable Reset IC
footprint SOT23-5_N (SOT23, 5-Leads, Body 2.9x1.6mm, Pitch 0.95mm, Lead Span 2.8mm, IPC Medium Density)
footprint SOT23-5_L (SOT23, 5-Leads, Body 2.9x1.6mm, Pitch 0.95mm, Lead Span 2.8mm, IPC High Density)
footprint SOT23-5_M (SOT23, 5-Leads, Body 2.9x1.6mm, Pitch 0.95mm, Lead Span 2.8mm, IPC Low Density)
pins: 1 ~{RST} (oc), 2 GND (power), 3 RST IN1 (in), 4 RST IN2 (in), 5 VCC (power)

## MAX6305UK00D4-T
designator U?
5-Pin, Multiple-Input, Programmable Reset IC
footprint SOT23-5_N (SOT23, 5-Leads, Body 2.9x1.6mm, Pitch 0.95mm, Lead Span 2.8mm, IPC Medium Density)
footprint SOT23-5_L (SOT23, 5-Leads, Body 2.9x1.6mm, Pitch 0.95mm, Lead Span 2.8mm, IPC High Density)
footprint SOT23-5_M (SOT23, 5-Leads, Body 2.9x1.6mm, Pitch 0.95mm, Lead Span 2.8mm, IPC Low Density)
pins: 1 ~{RST} (oc), 2 GND (power), 3 RST IN1 (in), 4 RST IN2 (in), 5 VCC (power)

## MAX6306UK25D1-T
designator U?
5-Pin, Multiple-Input, Programmable Reset IC
footprint SOT23-5_N (SOT23, 5-Leads, Body 2.9x1.6mm, Pitch 0.95mm, Lead Span 2.8mm, IPC Medium Density)
footprint SOT23-5_L (SOT23, 5-Leads, Body 2.9x1.6mm, Pitch 0.95mm, Lead Span 2.8mm, IPC High Density)
footprint SOT23-5_M (SOT23, 5-Leads, Body 2.9x1.6mm, Pitch 0.95mm, Lead Span 2.8mm, IPC Low Density)
pins: 1 ~{RST} (oc), 2 GND (power), 3 ~{MR} (in), 4 RST  IN (in), 5 VCC (power)

## MAX6306UK25D2-T
designator U?
5-Pin, Multiple-Input, Programmable Reset IC
footprint SOT23-5_N (SOT23, 5-Leads, Body 2.9x1.6mm, Pitch 0.95mm, Lead Span 2.8mm, IPC Medium Density)
footprint SOT23-5_L (SOT23, 5-Leads, Body 2.9x1.6mm, Pitch 0.95mm, Lead Span 2.8mm, IPC High Density)
footprint SOT23-5_M (SOT23, 5-Leads, Body 2.9x1.6mm, Pitch 0.95mm, Lead Span 2.8mm, IPC Low Density)
pins: 1 ~{RST} (oc), 2 GND (power), 3 ~{MR} (in), 4 RST  IN (in), 5 VCC (power)

## MAX6306UK25D3-T
designator U?
5-Pin, Multiple-Input, Programmable Reset IC
footprint SOT23-5_N (SOT23, 5-Leads, Body 2.9x1.6mm, Pitch 0.95mm, Lead Span 2.8mm, IPC Medium Density)
footprint SOT23-5_L (SOT23, 5-Leads, Body 2.9x1.6mm, Pitch 0.95mm, Lead Span 2.8mm, IPC High Density)
footprint SOT23-5_M (SOT23, 5-Leads, Body 2.9x1.6mm, Pitch 0.95mm, Lead Span 2.8mm, IPC Low Density)
pins: 1 ~{RST} (oc), 2 GND (power), 3 ~{MR} (in), 4 RST  IN (in), 5 VCC (power)

## MAX6306UK25D4-T
designator U?
5-Pin, Multiple-Input, Programmable Reset IC
footprint SOT23-5_N (SOT23, 5-Leads, Body 2.9x1.6mm, Pitch 0.95mm, Lead Span 2.8mm, IPC Medium Density)
footprint SOT23-5_L (SOT23, 5-Leads, Body 2.9x1.6mm, Pitch 0.95mm, Lead Span 2.8mm, IPC High Density)
footprint SOT23-5_M (SOT23, 5-Leads, Body 2.9x1.6mm, Pitch 0.95mm, Lead Span 2.8mm, IPC Low Density)
pins: 1 ~{RST} (oc), 2 GND (power), 3 ~{MR} (in), 4 RST  IN (in), 5 VCC (power)

## MAX6306UK26D1-T
designator U?
5-Pin, Multiple-Input, Programmable Reset IC
footprint SOT23-5_N (SOT23, 5-Leads, Body 2.9x1.6mm, Pitch 0.95mm, Lead Span 2.8mm, IPC Medium Density)
footprint SOT23-5_L (SOT23, 5-Leads, Body 2.9x1.6mm, Pitch 0.95mm, Lead Span 2.8mm, IPC High Density)
footprint SOT23-5_M (SOT23, 5-Leads, Body 2.9x1.6mm, Pitch 0.95mm, Lead Span 2.8mm, IPC Low Density)
pins: 1 ~{RST} (oc), 2 GND (power), 3 ~{MR} (in), 4 RST  IN (in), 5 VCC (power)

## MAX6306UK26D2-T
designator U?
5-Pin, Multiple-Input, Programmable Reset IC
footprint SOT23-5_N (SOT23, 5-Leads, Body 2.9x1.6mm, Pitch 0.95mm, Lead Span 2.8mm, IPC Medium Density)
footprint SOT23-5_L (SOT23, 5-Leads, Body 2.9x1.6mm, Pitch 0.95mm, Lead Span 2.8mm, IPC High Density)
footprint SOT23-5_M (SOT23, 5-Leads, Body 2.9x1.6mm, Pitch 0.95mm, Lead Span 2.8mm, IPC Low Density)
pins: 1 ~{RST} (oc), 2 GND (power), 3 ~{MR} (in), 4 RST  IN (in), 5 VCC (power)

## MAX6306UK26D3-T
designator U?
5-Pin, Multiple-Input, Programmable Reset IC
footprint SOT23-5_N (SOT23, 5-Leads, Body 2.9x1.6mm, Pitch 0.95mm, Lead Span 2.8mm, IPC Medium Density)
footprint SOT23-5_L (SOT23, 5-Leads, Body 2.9x1.6mm, Pitch 0.95mm, Lead Span 2.8mm, IPC High Density)
footprint SOT23-5_M (SOT23, 5-Leads, Body 2.9x1.6mm, Pitch 0.95mm, Lead Span 2.8mm, IPC Low Density)
pins: 1 ~{RST} (oc), 2 GND (power), 3 ~{MR} (in), 4 RST  IN (in), 5 VCC (power)

## MAX6306UK26D4-T
designator U?
5-Pin, Multiple-Input, Programmable Reset IC
footprint SOT23-5_N (SOT23, 5-Leads, Body 2.9x1.6mm, Pitch 0.95mm, Lead Span 2.8mm, IPC Medium Density)
footprint SOT23-5_L (SOT23, 5-Leads, Body 2.9x1.6mm, Pitch 0.95mm, Lead Span 2.8mm, IPC High Density)
footprint SOT23-5_M (SOT23, 5-Leads, Body 2.9x1.6mm, Pitch 0.95mm, Lead Span 2.8mm, IPC Low Density)
pins: 1 ~{RST} (oc), 2 GND (power), 3 ~{MR} (in), 4 RST  IN (in), 5 VCC (power)

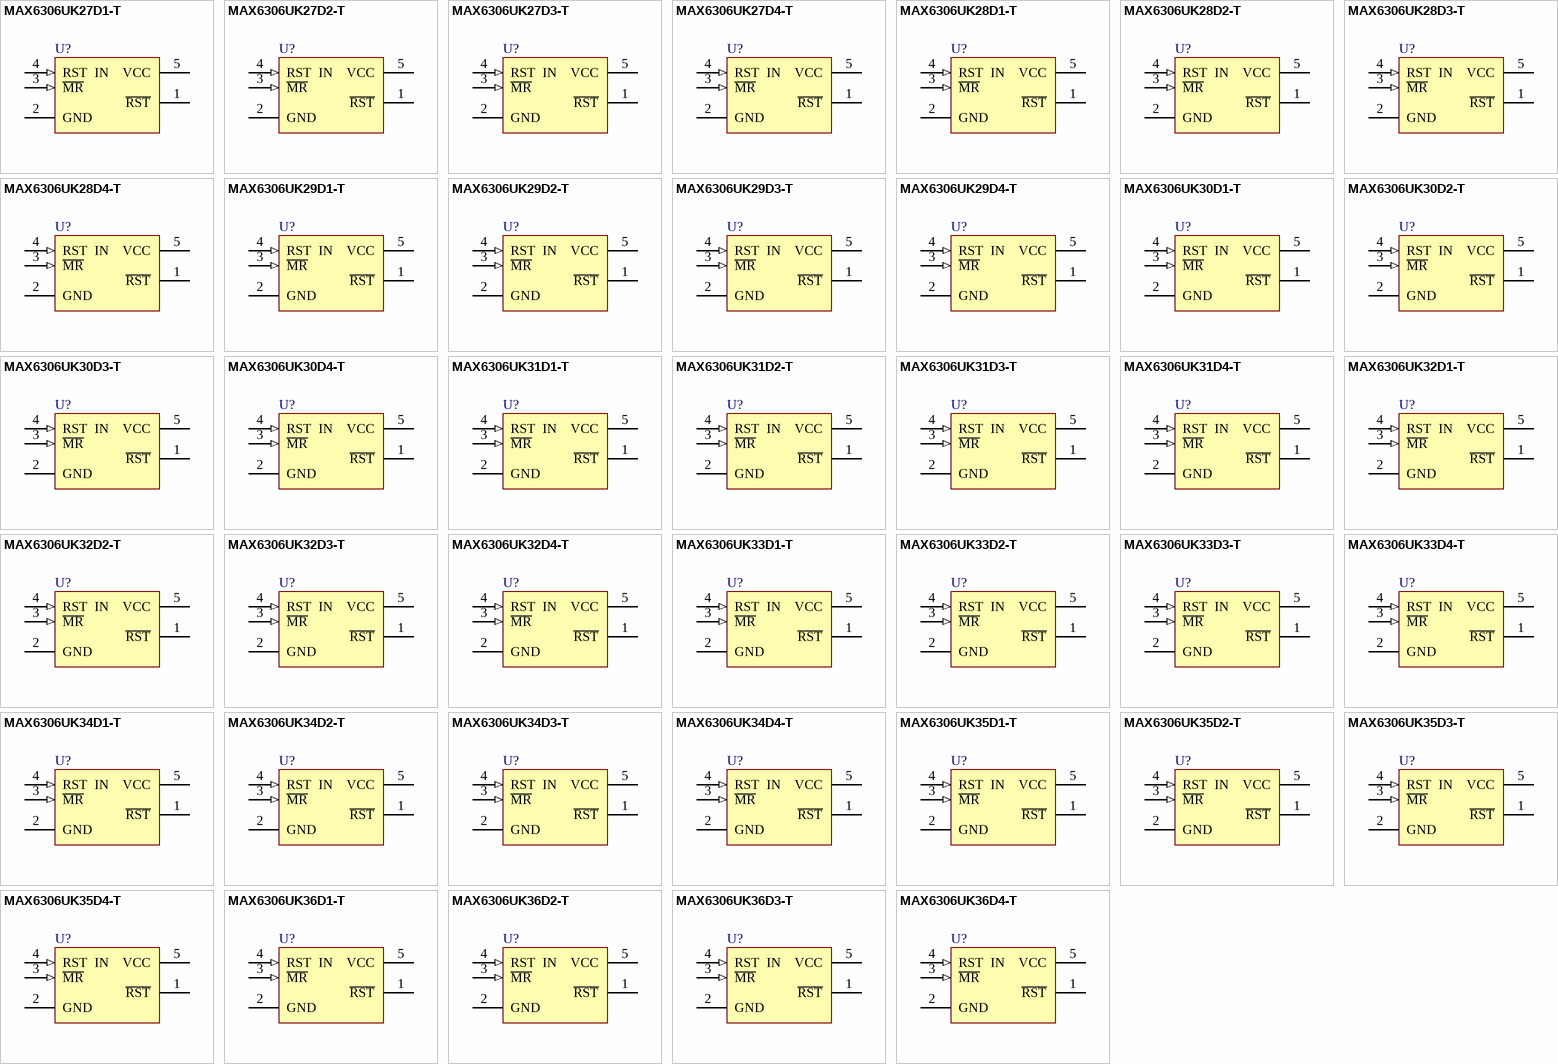
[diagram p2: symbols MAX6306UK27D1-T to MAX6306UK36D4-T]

## MAX6306UK27D1-T
designator U?
5-Pin, Multiple-Input, Programmable Reset IC
footprint SOT23-5_N (SOT23, 5-Leads, Body 2.9x1.6mm, Pitch 0.95mm, Lead Span 2.8mm, IPC Medium Density)
footprint SOT23-5_L (SOT23, 5-Leads, Body 2.9x1.6mm, Pitch 0.95mm, Lead Span 2.8mm, IPC High Density)
footprint SOT23-5_M (SOT23, 5-Leads, Body 2.9x1.6mm, Pitch 0.95mm, Lead Span 2.8mm, IPC Low Density)
pins: 1 ~{RST} (oc), 2 GND (power), 3 ~{MR} (in), 4 RST  IN (in), 5 VCC (power)

## MAX6306UK27D2-T
designator U?
5-Pin, Multiple-Input, Programmable Reset IC
footprint SOT23-5_N (SOT23, 5-Leads, Body 2.9x1.6mm, Pitch 0.95mm, Lead Span 2.8mm, IPC Medium Density)
footprint SOT23-5_L (SOT23, 5-Leads, Body 2.9x1.6mm, Pitch 0.95mm, Lead Span 2.8mm, IPC High Density)
footprint SOT23-5_M (SOT23, 5-Leads, Body 2.9x1.6mm, Pitch 0.95mm, Lead Span 2.8mm, IPC Low Density)
pins: 1 ~{RST} (oc), 2 GND (power), 3 ~{MR} (in), 4 RST  IN (in), 5 VCC (power)

## MAX6306UK27D3-T
designator U?
5-Pin, Multiple-Input, Programmable Reset IC
footprint SOT23-5_N (SOT23, 5-Leads, Body 2.9x1.6mm, Pitch 0.95mm, Lead Span 2.8mm, IPC Medium Density)
footprint SOT23-5_L (SOT23, 5-Leads, Body 2.9x1.6mm, Pitch 0.95mm, Lead Span 2.8mm, IPC High Density)
footprint SOT23-5_M (SOT23, 5-Leads, Body 2.9x1.6mm, Pitch 0.95mm, Lead Span 2.8mm, IPC Low Density)
pins: 1 ~{RST} (oc), 2 GND (power), 3 ~{MR} (in), 4 RST  IN (in), 5 VCC (power)

## MAX6306UK27D4-T
designator U?
5-Pin, Multiple-Input, Programmable Reset IC
footprint SOT23-5_N (SOT23, 5-Leads, Body 2.9x1.6mm, Pitch 0.95mm, Lead Span 2.8mm, IPC Medium Density)
footprint SOT23-5_L (SOT23, 5-Leads, Body 2.9x1.6mm, Pitch 0.95mm, Lead Span 2.8mm, IPC High Density)
footprint SOT23-5_M (SOT23, 5-Leads, Body 2.9x1.6mm, Pitch 0.95mm, Lead Span 2.8mm, IPC Low Density)
pins: 1 ~{RST} (oc), 2 GND (power), 3 ~{MR} (in), 4 RST  IN (in), 5 VCC (power)

## MAX6306UK28D1-T
designator U?
5-Pin, Multiple-Input, Programmable Reset IC
footprint SOT23-5_N (SOT23, 5-Leads, Body 2.9x1.6mm, Pitch 0.95mm, Lead Span 2.8mm, IPC Medium Density)
footprint SOT23-5_L (SOT23, 5-Leads, Body 2.9x1.6mm, Pitch 0.95mm, Lead Span 2.8mm, IPC High Density)
footprint SOT23-5_M (SOT23, 5-Leads, Body 2.9x1.6mm, Pitch 0.95mm, Lead Span 2.8mm, IPC Low Density)
pins: 1 ~{RST} (oc), 2 GND (power), 3 ~{MR} (in), 4 RST  IN (in), 5 VCC (power)

## MAX6306UK28D2-T
designator U?
5-Pin, Multiple-Input, Programmable Reset IC
footprint SOT23-5_N (SOT23, 5-Leads, Body 2.9x1.6mm, Pitch 0.95mm, Lead Span 2.8mm, IPC Medium Density)
footprint SOT23-5_L (SOT23, 5-Leads, Body 2.9x1.6mm, Pitch 0.95mm, Lead Span 2.8mm, IPC High Density)
footprint SOT23-5_M (SOT23, 5-Leads, Body 2.9x1.6mm, Pitch 0.95mm, Lead Span 2.8mm, IPC Low Density)
pins: 1 ~{RST} (oc), 2 GND (power), 3 ~{MR} (in), 4 RST  IN (in), 5 VCC (power)

## MAX6306UK28D3-T
designator U?
5-Pin, Multiple-Input, Programmable Reset IC
footprint SOT23-5_N (SOT23, 5-Leads, Body 2.9x1.6mm, Pitch 0.95mm, Lead Span 2.8mm, IPC Medium Density)
footprint SOT23-5_L (SOT23, 5-Leads, Body 2.9x1.6mm, Pitch 0.95mm, Lead Span 2.8mm, IPC High Density)
footprint SOT23-5_M (SOT23, 5-Leads, Body 2.9x1.6mm, Pitch 0.95mm, Lead Span 2.8mm, IPC Low Density)
pins: 1 ~{RST} (oc), 2 GND (power), 3 ~{MR} (in), 4 RST  IN (in), 5 VCC (power)

## MAX6306UK28D4-T
designator U?
5-Pin, Multiple-Input, Programmable Reset IC
footprint SOT23-5_N (SOT23, 5-Leads, Body 2.9x1.6mm, Pitch 0.95mm, Lead Span 2.8mm, IPC Medium Density)
footprint SOT23-5_L (SOT23, 5-Leads, Body 2.9x1.6mm, Pitch 0.95mm, Lead Span 2.8mm, IPC High Density)
footprint SOT23-5_M (SOT23, 5-Leads, Body 2.9x1.6mm, Pitch 0.95mm, Lead Span 2.8mm, IPC Low Density)
pins: 1 ~{RST} (oc), 2 GND (power), 3 ~{MR} (in), 4 RST  IN (in), 5 VCC (power)

## MAX6306UK29D1-T
designator U?
5-Pin, Multiple-Input, Programmable Reset IC
footprint SOT23-5_N (SOT23, 5-Leads, Body 2.9x1.6mm, Pitch 0.95mm, Lead Span 2.8mm, IPC Medium Density)
footprint SOT23-5_L (SOT23, 5-Leads, Body 2.9x1.6mm, Pitch 0.95mm, Lead Span 2.8mm, IPC High Density)
footprint SOT23-5_M (SOT23, 5-Leads, Body 2.9x1.6mm, Pitch 0.95mm, Lead Span 2.8mm, IPC Low Density)
pins: 1 ~{RST} (oc), 2 GND (power), 3 ~{MR} (in), 4 RST  IN (in), 5 VCC (power)

## MAX6306UK29D2-T
designator U?
5-Pin, Multiple-Input, Programmable Reset IC
footprint SOT23-5_N (SOT23, 5-Leads, Body 2.9x1.6mm, Pitch 0.95mm, Lead Span 2.8mm, IPC Medium Density)
footprint SOT23-5_L (SOT23, 5-Leads, Body 2.9x1.6mm, Pitch 0.95mm, Lead Span 2.8mm, IPC High Density)
footprint SOT23-5_M (SOT23, 5-Leads, Body 2.9x1.6mm, Pitch 0.95mm, Lead Span 2.8mm, IPC Low Density)
pins: 1 ~{RST} (oc), 2 GND (power), 3 ~{MR} (in), 4 RST  IN (in), 5 VCC (power)

## MAX6306UK29D3-T
designator U?
5-Pin, Multiple-Input, Programmable Reset IC
footprint SOT23-5_N (SOT23, 5-Leads, Body 2.9x1.6mm, Pitch 0.95mm, Lead Span 2.8mm, IPC Medium Density)
footprint SOT23-5_L (SOT23, 5-Leads, Body 2.9x1.6mm, Pitch 0.95mm, Lead Span 2.8mm, IPC High Density)
footprint SOT23-5_M (SOT23, 5-Leads, Body 2.9x1.6mm, Pitch 0.95mm, Lead Span 2.8mm, IPC Low Density)
pins: 1 ~{RST} (oc), 2 GND (power), 3 ~{MR} (in), 4 RST  IN (in), 5 VCC (power)

## MAX6306UK29D4-T
designator U?
5-Pin, Multiple-Input, Programmable Reset IC
footprint SOT23-5_N (SOT23, 5-Leads, Body 2.9x1.6mm, Pitch 0.95mm, Lead Span 2.8mm, IPC Medium Density)
footprint SOT23-5_L (SOT23, 5-Leads, Body 2.9x1.6mm, Pitch 0.95mm, Lead Span 2.8mm, IPC High Density)
footprint SOT23-5_M (SOT23, 5-Leads, Body 2.9x1.6mm, Pitch 0.95mm, Lead Span 2.8mm, IPC Low Density)
pins: 1 ~{RST} (oc), 2 GND (power), 3 ~{MR} (in), 4 RST  IN (in), 5 VCC (power)

## MAX6306UK30D1-T
designator U?
5-Pin, Multiple-Input, Programmable Reset IC
footprint SOT23-5_N (SOT23, 5-Leads, Body 2.9x1.6mm, Pitch 0.95mm, Lead Span 2.8mm, IPC Medium Density)
footprint SOT23-5_L (SOT23, 5-Leads, Body 2.9x1.6mm, Pitch 0.95mm, Lead Span 2.8mm, IPC High Density)
footprint SOT23-5_M (SOT23, 5-Leads, Body 2.9x1.6mm, Pitch 0.95mm, Lead Span 2.8mm, IPC Low Density)
pins: 1 ~{RST} (oc), 2 GND (power), 3 ~{MR} (in), 4 RST  IN (in), 5 VCC (power)

## MAX6306UK30D2-T
designator U?
5-Pin, Multiple-Input, Programmable Reset IC
footprint SOT23-5_N (SOT23, 5-Leads, Body 2.9x1.6mm, Pitch 0.95mm, Lead Span 2.8mm, IPC Medium Density)
footprint SOT23-5_L (SOT23, 5-Leads, Body 2.9x1.6mm, Pitch 0.95mm, Lead Span 2.8mm, IPC High Density)
footprint SOT23-5_M (SOT23, 5-Leads, Body 2.9x1.6mm, Pitch 0.95mm, Lead Span 2.8mm, IPC Low Density)
pins: 1 ~{RST} (oc), 2 GND (power), 3 ~{MR} (in), 4 RST  IN (in), 5 VCC (power)

## MAX6306UK30D3-T
designator U?
5-Pin, Multiple-Input, Programmable Reset IC
footprint SOT23-5_N (SOT23, 5-Leads, Body 2.9x1.6mm, Pitch 0.95mm, Lead Span 2.8mm, IPC Medium Density)
footprint SOT23-5_L (SOT23, 5-Leads, Body 2.9x1.6mm, Pitch 0.95mm, Lead Span 2.8mm, IPC High Density)
footprint SOT23-5_M (SOT23, 5-Leads, Body 2.9x1.6mm, Pitch 0.95mm, Lead Span 2.8mm, IPC Low Density)
pins: 1 ~{RST} (oc), 2 GND (power), 3 ~{MR} (in), 4 RST  IN (in), 5 VCC (power)

## MAX6306UK30D4-T
designator U?
5-Pin, Multiple-Input, Programmable Reset IC
footprint SOT23-5_N (SOT23, 5-Leads, Body 2.9x1.6mm, Pitch 0.95mm, Lead Span 2.8mm, IPC Medium Density)
footprint SOT23-5_L (SOT23, 5-Leads, Body 2.9x1.6mm, Pitch 0.95mm, Lead Span 2.8mm, IPC High Density)
footprint SOT23-5_M (SOT23, 5-Leads, Body 2.9x1.6mm, Pitch 0.95mm, Lead Span 2.8mm, IPC Low Density)
pins: 1 ~{RST} (oc), 2 GND (power), 3 ~{MR} (in), 4 RST  IN (in), 5 VCC (power)

## MAX6306UK31D1-T
designator U?
5-Pin, Multiple-Input, Programmable Reset IC
footprint SOT23-5_N (SOT23, 5-Leads, Body 2.9x1.6mm, Pitch 0.95mm, Lead Span 2.8mm, IPC Medium Density)
footprint SOT23-5_L (SOT23, 5-Leads, Body 2.9x1.6mm, Pitch 0.95mm, Lead Span 2.8mm, IPC High Density)
footprint SOT23-5_M (SOT23, 5-Leads, Body 2.9x1.6mm, Pitch 0.95mm, Lead Span 2.8mm, IPC Low Density)
pins: 1 ~{RST} (oc), 2 GND (power), 3 ~{MR} (in), 4 RST  IN (in), 5 VCC (power)

## MAX6306UK31D2-T
designator U?
5-Pin, Multiple-Input, Programmable Reset IC
footprint SOT23-5_N (SOT23, 5-Leads, Body 2.9x1.6mm, Pitch 0.95mm, Lead Span 2.8mm, IPC Medium Density)
footprint SOT23-5_L (SOT23, 5-Leads, Body 2.9x1.6mm, Pitch 0.95mm, Lead Span 2.8mm, IPC High Density)
footprint SOT23-5_M (SOT23, 5-Leads, Body 2.9x1.6mm, Pitch 0.95mm, Lead Span 2.8mm, IPC Low Density)
pins: 1 ~{RST} (oc), 2 GND (power), 3 ~{MR} (in), 4 RST  IN (in), 5 VCC (power)

## MAX6306UK31D3-T
designator U?
5-Pin, Multiple-Input, Programmable Reset IC
footprint SOT23-5_N (SOT23, 5-Leads, Body 2.9x1.6mm, Pitch 0.95mm, Lead Span 2.8mm, IPC Medium Density)
footprint SOT23-5_L (SOT23, 5-Leads, Body 2.9x1.6mm, Pitch 0.95mm, Lead Span 2.8mm, IPC High Density)
footprint SOT23-5_M (SOT23, 5-Leads, Body 2.9x1.6mm, Pitch 0.95mm, Lead Span 2.8mm, IPC Low Density)
pins: 1 ~{RST} (oc), 2 GND (power), 3 ~{MR} (in), 4 RST  IN (in), 5 VCC (power)

## MAX6306UK31D4-T
designator U?
5-Pin, Multiple-Input, Programmable Reset IC
footprint SOT23-5_N (SOT23, 5-Leads, Body 2.9x1.6mm, Pitch 0.95mm, Lead Span 2.8mm, IPC Medium Density)
footprint SOT23-5_L (SOT23, 5-Leads, Body 2.9x1.6mm, Pitch 0.95mm, Lead Span 2.8mm, IPC High Density)
footprint SOT23-5_M (SOT23, 5-Leads, Body 2.9x1.6mm, Pitch 0.95mm, Lead Span 2.8mm, IPC Low Density)
pins: 1 ~{RST} (oc), 2 GND (power), 3 ~{MR} (in), 4 RST  IN (in), 5 VCC (power)

## MAX6306UK32D1-T
designator U?
5-Pin, Multiple-Input, Programmable Reset IC
footprint SOT23-5_N (SOT23, 5-Leads, Body 2.9x1.6mm, Pitch 0.95mm, Lead Span 2.8mm, IPC Medium Density)
footprint SOT23-5_L (SOT23, 5-Leads, Body 2.9x1.6mm, Pitch 0.95mm, Lead Span 2.8mm, IPC High Density)
footprint SOT23-5_M (SOT23, 5-Leads, Body 2.9x1.6mm, Pitch 0.95mm, Lead Span 2.8mm, IPC Low Density)
pins: 1 ~{RST} (oc), 2 GND (power), 3 ~{MR} (in), 4 RST  IN (in), 5 VCC (power)

## MAX6306UK32D2-T
designator U?
5-Pin, Multiple-Input, Programmable Reset IC
footprint SOT23-5_N (SOT23, 5-Leads, Body 2.9x1.6mm, Pitch 0.95mm, Lead Span 2.8mm, IPC Medium Density)
footprint SOT23-5_L (SOT23, 5-Leads, Body 2.9x1.6mm, Pitch 0.95mm, Lead Span 2.8mm, IPC High Density)
footprint SOT23-5_M (SOT23, 5-Leads, Body 2.9x1.6mm, Pitch 0.95mm, Lead Span 2.8mm, IPC Low Density)
pins: 1 ~{RST} (oc), 2 GND (power), 3 ~{MR} (in), 4 RST  IN (in), 5 VCC (power)

## MAX6306UK32D3-T
designator U?
5-Pin, Multiple-Input, Programmable Reset IC
footprint SOT23-5_N (SOT23, 5-Leads, Body 2.9x1.6mm, Pitch 0.95mm, Lead Span 2.8mm, IPC Medium Density)
footprint SOT23-5_L (SOT23, 5-Leads, Body 2.9x1.6mm, Pitch 0.95mm, Lead Span 2.8mm, IPC High Density)
footprint SOT23-5_M (SOT23, 5-Leads, Body 2.9x1.6mm, Pitch 0.95mm, Lead Span 2.8mm, IPC Low Density)
pins: 1 ~{RST} (oc), 2 GND (power), 3 ~{MR} (in), 4 RST  IN (in), 5 VCC (power)

## MAX6306UK32D4-T
designator U?
5-Pin, Multiple-Input, Programmable Reset IC
footprint SOT23-5_N (SOT23, 5-Leads, Body 2.9x1.6mm, Pitch 0.95mm, Lead Span 2.8mm, IPC Medium Density)
footprint SOT23-5_L (SOT23, 5-Leads, Body 2.9x1.6mm, Pitch 0.95mm, Lead Span 2.8mm, IPC High Density)
footprint SOT23-5_M (SOT23, 5-Leads, Body 2.9x1.6mm, Pitch 0.95mm, Lead Span 2.8mm, IPC Low Density)
pins: 1 ~{RST} (oc), 2 GND (power), 3 ~{MR} (in), 4 RST  IN (in), 5 VCC (power)

## MAX6306UK33D1-T
designator U?
5-Pin, Multiple-Input, Programmable Reset IC
footprint SOT23-5_N (SOT23, 5-Leads, Body 2.9x1.6mm, Pitch 0.95mm, Lead Span 2.8mm, IPC Medium Density)
footprint SOT23-5_L (SOT23, 5-Leads, Body 2.9x1.6mm, Pitch 0.95mm, Lead Span 2.8mm, IPC High Density)
footprint SOT23-5_M (SOT23, 5-Leads, Body 2.9x1.6mm, Pitch 0.95mm, Lead Span 2.8mm, IPC Low Density)
pins: 1 ~{RST} (oc), 2 GND (power), 3 ~{MR} (in), 4 RST  IN (in), 5 VCC (power)

## MAX6306UK33D2-T
designator U?
5-Pin, Multiple-Input, Programmable Reset IC
footprint SOT23-5_N (SOT23, 5-Leads, Body 2.9x1.6mm, Pitch 0.95mm, Lead Span 2.8mm, IPC Medium Density)
footprint SOT23-5_L (SOT23, 5-Leads, Body 2.9x1.6mm, Pitch 0.95mm, Lead Span 2.8mm, IPC High Density)
footprint SOT23-5_M (SOT23, 5-Leads, Body 2.9x1.6mm, Pitch 0.95mm, Lead Span 2.8mm, IPC Low Density)
pins: 1 ~{RST} (oc), 2 GND (power), 3 ~{MR} (in), 4 RST  IN (in), 5 VCC (power)

## MAX6306UK33D3-T
designator U?
5-Pin, Multiple-Input, Programmable Reset IC
footprint SOT23-5_N (SOT23, 5-Leads, Body 2.9x1.6mm, Pitch 0.95mm, Lead Span 2.8mm, IPC Medium Density)
footprint SOT23-5_L (SOT23, 5-Leads, Body 2.9x1.6mm, Pitch 0.95mm, Lead Span 2.8mm, IPC High Density)
footprint SOT23-5_M (SOT23, 5-Leads, Body 2.9x1.6mm, Pitch 0.95mm, Lead Span 2.8mm, IPC Low Density)
pins: 1 ~{RST} (oc), 2 GND (power), 3 ~{MR} (in), 4 RST  IN (in), 5 VCC (power)

## MAX6306UK33D4-T
designator U?
5-Pin, Multiple-Input, Programmable Reset IC
footprint SOT23-5_N (SOT23, 5-Leads, Body 2.9x1.6mm, Pitch 0.95mm, Lead Span 2.8mm, IPC Medium Density)
footprint SOT23-5_L (SOT23, 5-Leads, Body 2.9x1.6mm, Pitch 0.95mm, Lead Span 2.8mm, IPC High Density)
footprint SOT23-5_M (SOT23, 5-Leads, Body 2.9x1.6mm, Pitch 0.95mm, Lead Span 2.8mm, IPC Low Density)
pins: 1 ~{RST} (oc), 2 GND (power), 3 ~{MR} (in), 4 RST  IN (in), 5 VCC (power)

## MAX6306UK34D1-T
designator U?
5-Pin, Multiple-Input, Programmable Reset IC
footprint SOT23-5_N (SOT23, 5-Leads, Body 2.9x1.6mm, Pitch 0.95mm, Lead Span 2.8mm, IPC Medium Density)
footprint SOT23-5_L (SOT23, 5-Leads, Body 2.9x1.6mm, Pitch 0.95mm, Lead Span 2.8mm, IPC High Density)
footprint SOT23-5_M (SOT23, 5-Leads, Body 2.9x1.6mm, Pitch 0.95mm, Lead Span 2.8mm, IPC Low Density)
pins: 1 ~{RST} (oc), 2 GND (power), 3 ~{MR} (in), 4 RST  IN (in), 5 VCC (power)

## MAX6306UK34D2-T
designator U?
5-Pin, Multiple-Input, Programmable Reset IC
footprint SOT23-5_N (SOT23, 5-Leads, Body 2.9x1.6mm, Pitch 0.95mm, Lead Span 2.8mm, IPC Medium Density)
footprint SOT23-5_L (SOT23, 5-Leads, Body 2.9x1.6mm, Pitch 0.95mm, Lead Span 2.8mm, IPC High Density)
footprint SOT23-5_M (SOT23, 5-Leads, Body 2.9x1.6mm, Pitch 0.95mm, Lead Span 2.8mm, IPC Low Density)
pins: 1 ~{RST} (oc), 2 GND (power), 3 ~{MR} (in), 4 RST  IN (in), 5 VCC (power)

## MAX6306UK34D3-T
designator U?
5-Pin, Multiple-Input, Programmable Reset IC
footprint SOT23-5_N (SOT23, 5-Leads, Body 2.9x1.6mm, Pitch 0.95mm, Lead Span 2.8mm, IPC Medium Density)
footprint SOT23-5_L (SOT23, 5-Leads, Body 2.9x1.6mm, Pitch 0.95mm, Lead Span 2.8mm, IPC High Density)
footprint SOT23-5_M (SOT23, 5-Leads, Body 2.9x1.6mm, Pitch 0.95mm, Lead Span 2.8mm, IPC Low Density)
pins: 1 ~{RST} (oc), 2 GND (power), 3 ~{MR} (in), 4 RST  IN (in), 5 VCC (power)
